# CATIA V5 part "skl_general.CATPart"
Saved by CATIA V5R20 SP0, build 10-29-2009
Part number: skl_general
Property "Longueur_AB_FC_DE": 200 mm
Property "Longueur_BC_FA": 100 mm
Property "Longueur_CD_EF": 120 mm
Publications: "Longueur_AB_FC_DE", "Longueur_BC_FA", "Longueur_CD_EF", "Plan_Ref", "Point_F", "Point_A", "Point_E", "Point_B", "Point_D", "Point_C"
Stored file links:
  D:\Dropbox\IAO_2012\IAO_2012_742_prousseau\skl_general.CATPart

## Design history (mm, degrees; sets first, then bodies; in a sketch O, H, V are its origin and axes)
Parameters
  Longueur_AB_FC_DE = 200 mm
  Longueur_BC_FA = 100 mm
  Longueur_CD_EF = 120 mm
Set1
  Plane1 "Plan_Ref": type Offset, RefPlane yz-plane, Offset 0
  Point1 "Point_F": type OnPlane, Support Plane1, H 0, V 0, Direction (0, 1, 0)
  Point2 "Point_A": type OnPlane, Support Plane1, H -80, V 50, Direction (0, 1, 0)
  Point3 "Point_E": type OnPlane, Support Plane1, H 100, V 50, Direction (0, 1, 0)
  Point4 "Point_B": type OnPlane, Support Plane1, H -55, V 200, Direction (0, 1, 0)
  Point5 "Point_D": type OnPlane, Support Plane1, H 125, V 200, Direction (0, 1, 0)
  Point6 "Point_C": type OnPlane, Support Plane1, H 25, V 150, Direction (0, 1, 0)
  Point7 "Point_O": type OnPlane, Support Plane1, H -17.981, V -35.251, Direction (0, 1, 0)
Body1 (main body)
